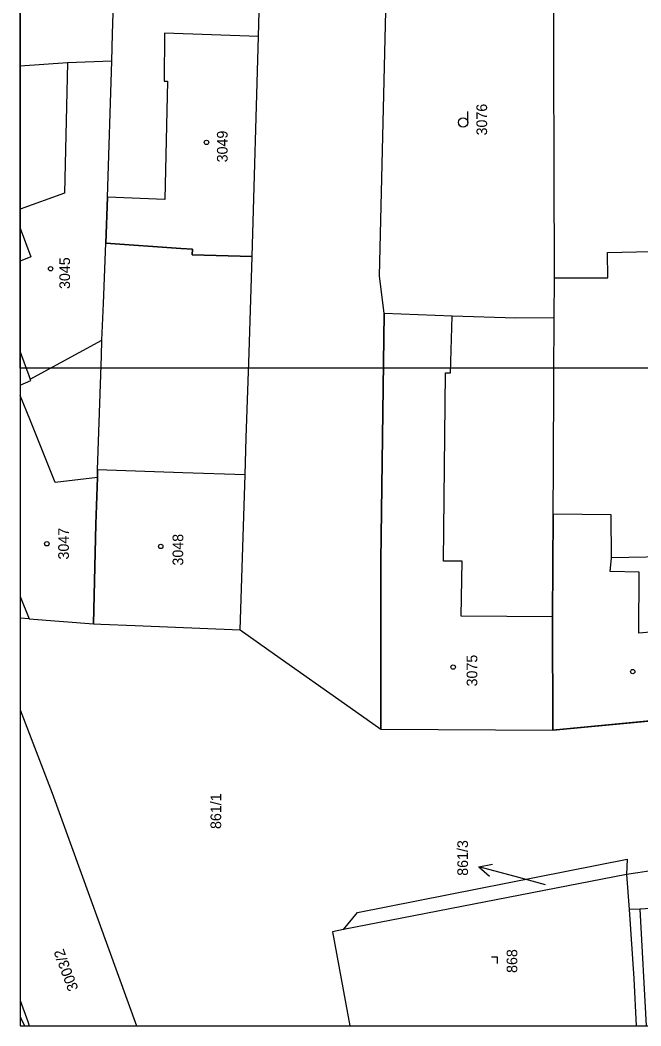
# Model space of a CAD drawing. Extents: x -534410 to -534262, y -1190162 to -1189584.
# Drawn here: x -534410.1 to -534360.6, y -1190162 to -1190081.7 of the extents above; entities that cross this region are included whole.
import ezdxf

# ---------------------------------------------------------------- set-up
doc = ezdxf.new("R2010")
doc.units = 0
for name, color, linetype in [('_rámeček', 7, 'Continuous'), ('_rámeček_mřížka', 7, 'Continuous'), ('Hranice parcel', 7, 'Continuous'), ('Parcelní čísla', 7, 'Continuous'), ('Polygon budovy', 7, 'Continuous'), ('Pop  PČ popisy', 7, 'Continuous'), ('Značky budov', 7, 'Continuous'), ('Značky kultur', 7, 'Continuous')]:
    doc.layers.add(name, color=color, linetype=linetype)

msp = doc.modelspace()

# ---------------------------------------------------------------- linework, layer by layer
at = {"layer": '_rámeček'}
msp.add_line((-534410.126, -1189584.47), (-534410.126, -1190161.97), dxfattribs=at)
msp.add_lwpolyline([(-534410.126, -1190161.97), (-534261.626, -1190161.97), (-534261.626, -1189584.47)], dxfattribs=at)
msp.add_lwpolyline([(-534410.126, -1190004.47), (-534261.626, -1190004.47), (-534261.626, -1190109.47), (-534410.126, -1190109.47)], close=True, dxfattribs=at)
at = {"layer": '_rámeček_mřížka'}
for p, q in [((-534410.126, -1189584.47), (-534410.126, -1190161.97)), ((-534407.126, -1190109.47), (-534410.126, -1190109.47))]:
    msp.add_line(p, q, dxfattribs=at)
msp.add_lwpolyline([(-534410.126, -1190161.97), (-534261.626, -1190161.97), (-534261.626, -1189584.47)], dxfattribs=at)
at = {"layer": 'Hranice parcel'}
for p, q in [((-534367.49, -1190105.45), (-534367.47, -1190102.26)), ((-534410.126, -1190127.686), (-534409.39, -1190129.48)), ((-534409.39, -1190129.48), (-534404.27, -1190129.87)), ((-534351.82, -1190136.86), (-534367.59, -1190138.36)), ((-534381.34, -1190138.28), (-534367.59, -1190138.36)), ((-534361.7, -1190149.89), (-534384.3, -1190154.28)), ((-534361.7, -1190149.89), (-534361.51, -1190152.68)), ((-534409.52, -1190161.62), (-534409.404, -1190161.97))]:
    msp.add_line(p, q, dxfattribs=at)
for points in [[(-534367.47, -1190102.26), (-534367.55, -1190076.15), (-534367.56, -1190073.35)], [(-534402.81, -1190084.96), (-534402.74, -1190082.76), (-534402.48, -1190074.44)], [(-534391.6, -1190100.55), (-534391.1, -1190082.99), (-534391.04, -1190081), (-534390.83, -1190074.99)], [(-534381.06, -1190105.11), (-534381.43, -1190102.09), (-534380.79, -1190075.34)], [(-534402.81, -1190084.96), (-534406.34, -1190085.09), (-534410.126, -1190085.355)], [(-534403.27, -1190099.48), (-534403.15, -1190095.8), (-534402.81, -1190084.96)], [(-534403.6, -1190107.23), (-534403.48, -1190104.31), (-534403.27, -1190099.48)], [(-534391.6, -1190100.55), (-534396.4, -1190100.41), (-534396.37, -1190099.97), (-534397.3, -1190099.9), (-534403.27, -1190099.48)], [(-534367.47, -1190102.26), (-534363.21, -1190102.26), (-534363.24, -1190100.22), (-534359.78, -1190100.14), (-534342.85, -1190101.1)], [(-534392.57, -1190130.35), (-534392.17, -1190117.99), (-534392.07, -1190115.02), (-534391.85, -1190108.23), (-534391.6, -1190100.55)], [(-534381.34, -1190138.28), (-534381.33, -1190124.85), (-534381.06, -1190105.11)], [(-534367.49, -1190105.45), (-534370.56, -1190105.46), (-534375.64, -1190105.3), (-534381.06, -1190105.11)], [(-534367.57, -1190121.12), (-534367.57, -1190120.94), (-534367.55, -1190117.44), (-534367.51, -1190110.01), (-534367.49, -1190105.45)], [(-534410.126, -1190110.828), (-534409.28, -1190110.45), (-534409.33, -1190110.33), (-534403.6, -1190107.23)], [(-534404.27, -1190129.87), (-534404.08, -1190121.91), (-534403.96, -1190118.2), (-534403.94, -1190117.57), (-534403.64, -1190108.48), (-534403.6, -1190107.23)], [(-534367.59, -1190138.36), (-534367.61, -1190129.31), (-534367.57, -1190121.12)], [(-534351.82, -1190136.86), (-534352.07, -1190129.87), (-534352.17, -1190126.76), (-534357.34, -1190124.5), (-534362.92, -1190124.6), (-534362.95, -1190121.17), (-534367.57, -1190121.12)], [(-534409.39, -1190129.48), (-534410.126, -1190129.421)], [(-534404.27, -1190129.87), (-534403.67, -1190129.9), (-534400.93, -1190130.01), (-534392.57, -1190130.35)], [(-534392.57, -1190130.35), (-534389.82, -1190132.3), (-534383.78, -1190136.56), (-534381.34, -1190138.28)], [(-534410.126, -1190136.737), (-534407.57, -1190143.38), (-534400.837, -1190161.97)], [(-534384.3, -1190154.28), (-534383.2, -1190152.93), (-534361.66, -1190148.66), (-534361.7, -1190149.89)], [(-534356.66, -1190149.1), (-534360.81, -1190149.75), (-534361.7, -1190149.89)], [(-534356.53, -1190152.42), (-534360.66, -1190152.64), (-534361.51, -1190152.68)], [(-534361.51, -1190152.68), (-534361.14, -1190158.2), (-534360.932, -1190161.97)], [(-534384.3, -1190154.28), (-534385.19, -1190154.45), (-534383.811, -1190161.97)], [(-534410.126, -1190159.936), (-534409.52, -1190161.62)], [(-534410.126, -1190161.266), (-534410.04, -1190161.42), (-534409.785, -1190161.97)]]:
    msp.add_lwpolyline(points, dxfattribs=at)
at = {"layer": 'Polygon budovy'}
for p, q in [((-534410.126, -1190096.76), (-534410.126, -1190098.275)), ((-534410.126, -1190100.914), (-534410.126, -1190108.147)), ((-534410.126, -1190111.636), (-534410.126, -1190127.686))]:
    msp.add_line(p, q, dxfattribs=at)
for points in [[(-534398.59, -1190082.73), (-534398.63, -1190086.56), (-534398.35, -1190086.56), (-534398.56, -1190096.01), (-534403.15, -1190095.8), (-534403.27, -1190099.48), (-534397.3, -1190099.9), (-534396.37, -1190099.97), (-534396.4, -1190100.41), (-534391.6, -1190100.55), (-534391.1, -1190082.99)], [(-534381.34, -1190138.28), (-534367.59, -1190138.36), (-534367.61, -1190129.31), (-534374.9, -1190129.27), (-534374.84, -1190124.88), (-534376.33, -1190124.88), (-534376.16, -1190109.83), (-534375.77, -1190109.83), (-534375.64, -1190105.3), (-534381.06, -1190105.11), (-534381.33, -1190124.85)], [(-534392.57, -1190130.35), (-534392.17, -1190117.99), (-534397.14, -1190117.81), (-534403.94, -1190117.57), (-534403.96, -1190118.2), (-534404.08, -1190121.91), (-534404.27, -1190129.87), (-534403.67, -1190129.9), (-534400.93, -1190130.01)], [(-534351.82, -1190136.86), (-534352.07, -1190129.87), (-534360.72, -1190130.62), (-534360.69, -1190125.75), (-534363.02, -1190125.69), (-534362.92, -1190124.6), (-534362.95, -1190121.17), (-534367.57, -1190121.12), (-534367.61, -1190129.31), (-534367.59, -1190138.36)]]:
    msp.add_lwpolyline(points, close=True, dxfattribs=at)
for points in [[(-534410.126, -1190108.147), (-534409.33, -1190110.33), (-534403.6, -1190107.23), (-534403.48, -1190104.31), (-534403.27, -1190099.48), (-534403.15, -1190095.8), (-534402.81, -1190084.96), (-534406.34, -1190085.09), (-534406.59, -1190095.5), (-534410.126, -1190096.76)], [(-534410.126, -1190098.275), (-534409.26, -1190100.57), (-534410.126, -1190100.914)], [(-534410.126, -1190127.686), (-534409.39, -1190129.48), (-534404.27, -1190129.87), (-534404.08, -1190121.91), (-534403.96, -1190118.2), (-534407.34, -1190118.6), (-534409.31, -1190113.68), (-534410.126, -1190111.636)], [(-534352.903, -1190161.97), (-534353.43, -1190152.26), (-534353.54, -1190152.27), (-534356.53, -1190152.42), (-534360.66, -1190152.64), (-534360.154, -1190161.97)]]:
    msp.add_lwpolyline(points, dxfattribs=at)
at = {"layer": 'Pop  PČ popisy'}
for p, q in [((-534373.499, -1190149.273), (-534372.402, -1190149.049)), ((-534370.6, -1190150.05), (-534373.499, -1190149.273)), ((-534373.499, -1190149.273), (-534372.661, -1190150.016)), ((-534368.19, -1190150.7), (-534370.6, -1190150.05))]:
    msp.add_line(p, q, dxfattribs=at)
at = {"layer": 'Značky budov'}
for centre in [(-534395.245, -1190091.441), (-534407.691, -1190101.521), (-534407.992, -1190123.483), (-534398.895, -1190123.697), (-534375.551, -1190133.328), (-534361.213, -1190133.688)]:
    msp.add_circle(centre, 0.175, dxfattribs=at)
at = {"layer": 'Značky kultur'}
for p, q in [((-534374.381, -1190089.847), (-534374.381, -1190088.972)), ((-534372.002, -1190156.476), (-534372.502, -1190156.476)), ((-534372.002, -1190156.977), (-534372.002, -1190156.476))]:
    msp.add_line(p, q, dxfattribs=at)
msp.add_circle((-534374.756, -1190089.847), 0.375, dxfattribs=at)

# ---------------------------------------------------------------- texts
at = {"layer": 'Parcelní čísla'}
for s, rotation, p in [('3076', 90, (-534372.843, -1190090.884)), ('3049', 90, (-534393.56, -1190093.032)), ('3045', 90, (-534406.143, -1190103.143)), ('3047', 90, (-534406.234, -1190124.736)), ('3048', 90, (-534397.104, -1190125.221)), ('3075', 90, (-534373.625, -1190134.87)), ('861/1', 90, (-534394.074, -1190146.253)), ('861/3', 90, (-534374.37, -1190149.987)), ('3003/2', 110.39285, (-534405.46, -1190159.007)), ('868', 90, (-534370.432, -1190157.742))]:
    msp.add_text(s, height=0.85, rotation=rotation, dxfattribs=at).set_placement(p)

doc.saveas('drawing.dxf')
